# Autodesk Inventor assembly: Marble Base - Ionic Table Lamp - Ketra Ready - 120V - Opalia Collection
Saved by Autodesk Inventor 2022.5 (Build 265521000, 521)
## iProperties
Created: 2025-02
Part Number: Marble Base - Ionic Table Lamp - Ketra Ready - 120V - Opalia Collection
Document SubType Name: Assembly
Designer: AdminForWorker
Title: Marble Base - Ionic Table Lamp - Ketra Ready - 120V - Opalia Collection v31
Author: AdminForWorker
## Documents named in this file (4)
- c:\worker\convert-fusion-r06-cosv3\tmp\job-1\154\temp\files\f1c30072-313d-4739-8c53-79efa0d23b5e\df8ffdc4-f544-4022-b76e-f65544ddf8dd.iam
- c:\worker\convert-fusion-r06-cosv3\tmp\job-1\154\temp\files\f1c30072-313d-4739-8c53-79efa0d23b5e\Marble Base - Ionic Table Lamp - Ketra Ready - 120V v17.iam
- c:\worker\convert-fusion-r06-cosv3\tmp\job-1\154\temp\files\f1c30072-313d-4739-8c53-79efa0d23b5e\Ketra - A20 Tunable Lamp v4.iam
- c:\worker\convert-fusion-r06-cosv3\tmp\job-1\154\temp\files\f1c30072-313d-4739-8c53-79efa0d23b5e\Dart Petite.ipt
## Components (3 placed, 3 different names)
1. Marble Base - Ionic Table Lamp - Ketra Ready - 120V v17:1 [sub-assembly]
2. Ketra - A20 Tunable Lamp v4:1 [sub-assembly]
3. Dart Petite:1
